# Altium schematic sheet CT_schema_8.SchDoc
size 385 x 278 mm
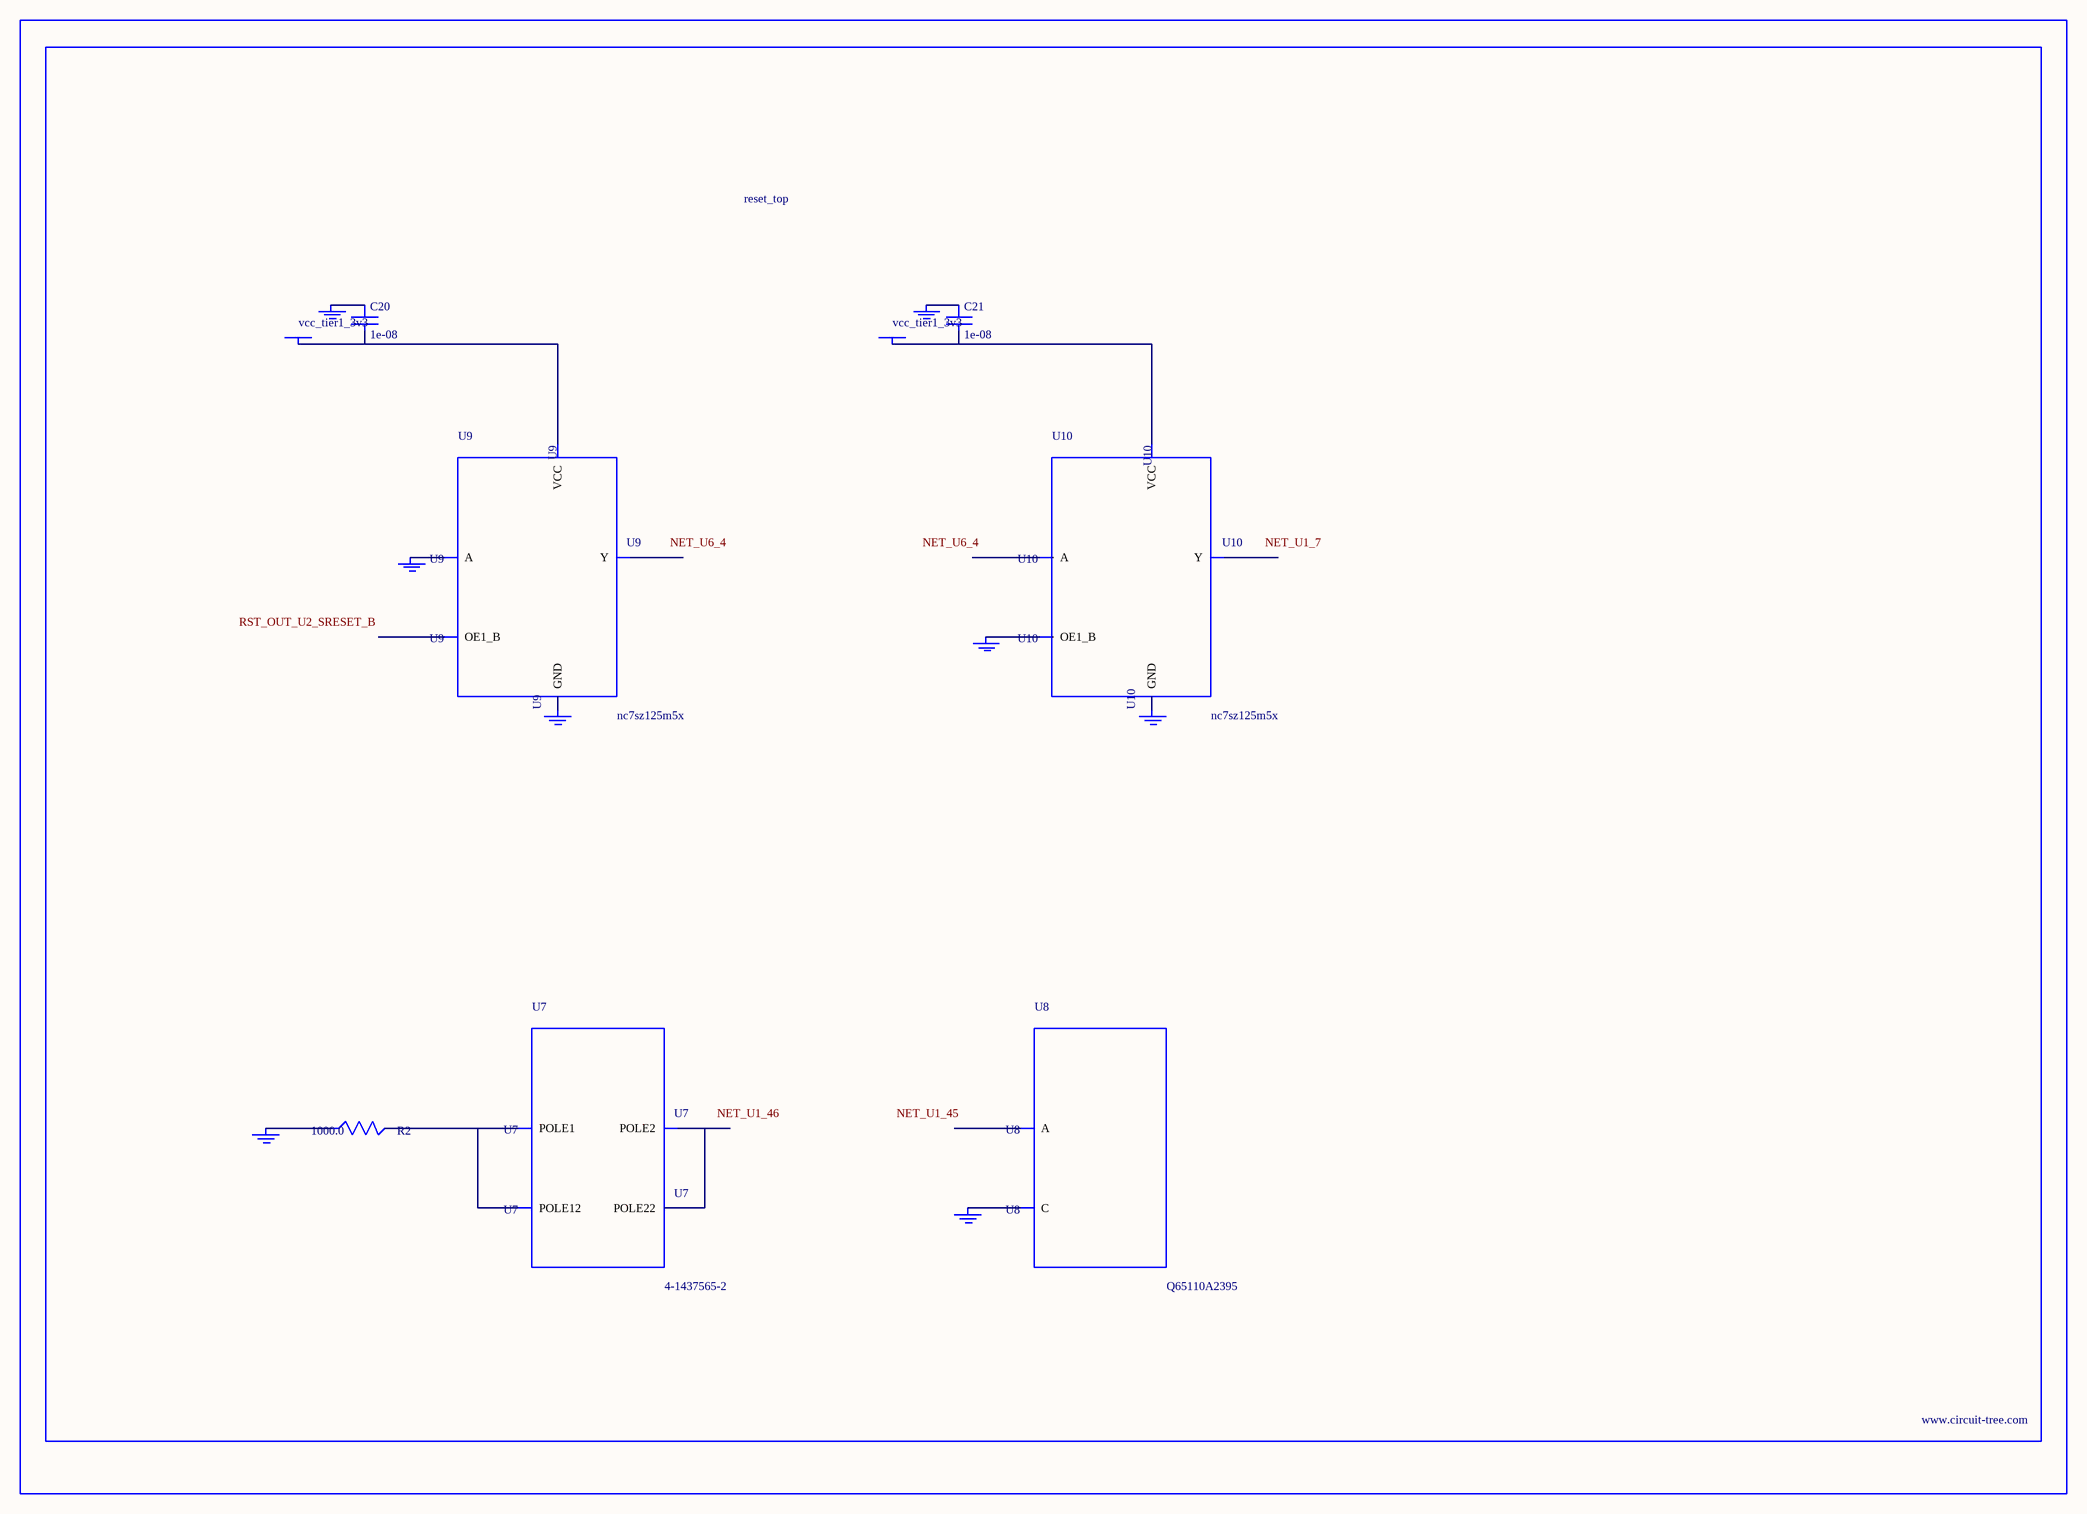
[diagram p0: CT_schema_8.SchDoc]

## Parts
BORDER7  (no value)
C20  1e-08  [C0402]
C21  1e-08  [C0402]
GND_INSTANCE_7_0  (no value)
GND_INSTANCE_7_1  (no value)
GND_INSTANCE_7_2  (no value)
GND_INSTANCE_7_3  (no value)
GND_INSTANCE_7_4  (no value)
GND_INSTANCE_7_5  (no value)
GND_INSTANCE_7_6  (no value)
GND_INSTANCE_7_7  (no value)
POWER_INSTANCE_7_0  vcc_tier1_3v3
POWER_INSTANCE_7_1  vcc_tier1_3v3
R2  1000.0  [R0603]
U7  4-1437565-2  [SW_4-1437565-2]
U8  Q65110A2395  [LGM67K-G1J2-24-Z]
U9  nc7sz125m5x  [NC7SZ125M5X]
U10  nc7sz125m5x  [NC7SZ125M5X]

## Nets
NetC20_1: C20.1 GND_INSTANCE_7_2.0(GND)
NetC20_2: C20.2 POWER_INSTANCE_7_0.0(PWR) U9.5(VCC)
NetC21_1: C21.1 GND_INSTANCE_7_5.0(GND)
NetC21_2: C21.2 POWER_INSTANCE_7_1.0(PWR) U10.5(VCC)
NetGND_INSTANCE_7_0_0: GND_INSTANCE_7_0.0(GND) R2.1
NetGND_INSTANCE_7_1_0: GND_INSTANCE_7_1.0(GND) U8.C
NetGND_INSTANCE_7_3_0: GND_INSTANCE_7_3.0(GND) U9.2(A)
NetGND_INSTANCE_7_4_0: GND_INSTANCE_7_4.0(GND) U9.3(GND)
NetGND_INSTANCE_7_6_0: GND_INSTANCE_7_6.0(GND) U10.1(OE1_B)
NetGND_INSTANCE_7_7_0: GND_INSTANCE_7_7.0(GND) U10.3(GND)
NetR2_2: R2.2 U7.1(POLE1) U7.2(POLE12)
NetU7_3: U7.3(POLE2) U7.4(POLE22)

Not connected (* = marked no-connect by the designer): U8 A; U9 1(OE1_B) 4(Y); U10 2(A) 4(Y)

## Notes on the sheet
- Labels drawn without touching a wire or pin: NET_U1_7, NET_U1_45, NET_U1_46, NET_U6_4, RST_OUT_U2_SRESET_B

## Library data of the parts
BORDER7 = BORDER_PAGE7
C20 C21 = C0402C103K3RAC
GND_INSTANCE_7_0-GND_INSTANCE_7_7 = GND
POWER_INSTANCE_7_0 POWER_INSTANCE_7_1 = PWR
R2 = RC0603JR-071KL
